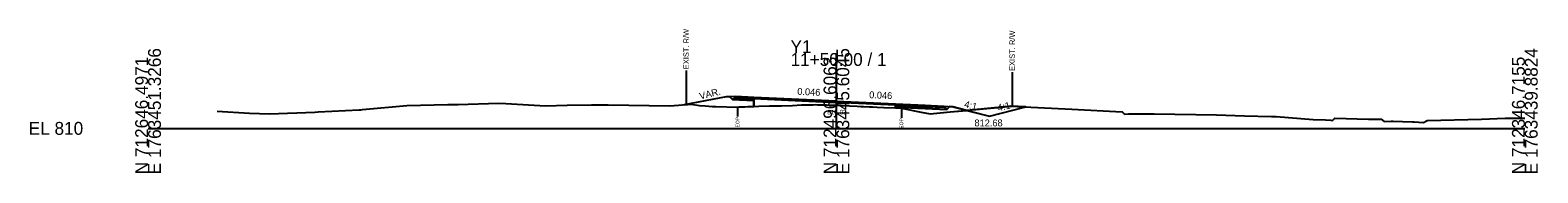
# Model space of a CAD drawing. Extents: x -26 to 1303, y -10 to 9524.
# Drawn here: x -25.7 to 302.8, y 1490.3 to 1521.4 of the extents above; entities that cross this region are included whole.
import ezdxf

# ---------------------------------------------------------------- set-up
doc = ezdxf.new("R2010")
doc.units = 0
for name, color, linetype in [('Default', 7, 'Continuous'), ('Exist CMT Pavement', 7, 'Continuous'), ('Exist Cross Section Cell', 7, 'Continuous'), ('Exist XS Center Line Elevation Label', 7, 'Continuous'), ('Exist XS Ground Line', 7, 'Continuous'), ('Old_Level_10', 7, 'Continuous'), ('Prop CMT Pvmt Course 1', 7, 'Continuous'), ('Prop CMT Pvmt Course 3', 7, 'Continuous'), ('Prop CMT Pvmt Surface', 7, 'Continuous'), ('Prop CMT Pvmt Surface Shoulder', 7, 'Continuous'), ('Prop CMT Shld Paved Course 1', 7, 'Continuous'), ('Prop CMT Shld Paved Course 3', 7, 'Continuous'), ('Prop CMT Slope Grass', 7, 'Continuous'), ('Prop CMT Subgrade Earthwork', 7, 'Continuous'), ('Prop XS Ditch Standard Text', 7, 'Continuous'), ('Prop XS Earthwork Shape', 7, 'Continuous'), ('Prop XS SE Text', 7, 'Continuous'), ('Prop XS Side Slope Text', 7, 'Continuous'), ('Prop XS Wedging', 7, 'Continuous')]:
    doc.layers.add(name, color=color, linetype=linetype)

msp = doc.modelspace()

# ---------------------------------------------------------------- linework, layer by layer
at = {"layer": 'Exist CMT Pavement'}
msp.add_lwpolyline([(132, 1504.78), (133.08, 1504.81), (135.44, 1504.9), (138.04, 1504.94), (140.4, 1505.01), (142.37, 1505.09), (143.9, 1505.11), (144.9, 1505.15), (145.35, 1505.16), (145.84, 1505.14), (147.85, 1505.09), (148.44, 1505.07), (150, 1505.03), (150.36, 1505.02), (151.04, 1504.98), (152.86, 1504.88), (154.54, 1504.82), (155.28, 1504.79), (155.9, 1504.75), (157.19, 1504.7), (157.86, 1504.67), (158.85, 1504.62), (160.36, 1504.56), (162.84, 1504.46), (162.84, 1504.46)], dxfattribs=at)
at = {"layer": 'Exist Cross Section Cell'}
for p, q in [((150, 1500), (150, 1516.4)), ((0, 1500), (150, 1500)), ((150, 1500), (300, 1500))]:
    msp.add_line(p, q, dxfattribs=at)
at = {"layer": 'Exist XS Ground Line'}
msp.add_lwpolyline([(15.03, 1503.71), (22.12, 1503.3), (26.44, 1503.14), (36.35, 1503.54), (37.08, 1503.57), (46.02, 1504.03), (46.36, 1504.07), (46.73, 1504.09), (56.37, 1504.98), (65.3, 1505.17), (66.38, 1505.2), (67.54, 1505.18), (76.39, 1505.47), (77.95, 1505.43), (86.62, 1504.9), (91.31, 1505.06), (96.63, 1505.14), (100.29, 1505.15), (113.66, 1504.93), (118.31, 1505.26), (120.16, 1505), (121.43, 1504.92), (123.02, 1504.75), (123.7, 1504.73), (128.45, 1504.65), (128.79, 1504.67), (129.55, 1504.69), (130.03, 1504.72), (130.71, 1504.75), (131.17, 1504.75), (133.08, 1504.81), (135.44, 1504.9), (138.04, 1504.94), (140.4, 1505.01), (142.37, 1505.09), (143.9, 1505.11), (144.9, 1505.15), (145.35, 1505.16), (145.84, 1505.14), (147.85, 1505.09), (148.44, 1505.07), (150, 1505.03), (150.36, 1505.02), (151.04, 1504.98), (152.86, 1504.88), (154.54, 1504.82), (155.28, 1504.79), (155.9, 1504.75), (157.19, 1504.7), (157.86, 1504.67), (158.85, 1504.62), (160.36, 1504.56), (162.84, 1504.46), (164.16, 1504.37), (168.44, 1503.55), (170.45, 1503.18), (174.78, 1503.58), (185.95, 1504.63), (187.24, 1504.74), (187.96, 1504.83), (201.28, 1504.18), (212.23, 1503.57), (212.74, 1503.07), (213.66, 1503.14), (214.26, 1503.17), (219.25, 1503.19), (232.81, 1502.92), (238.92, 1502.74), (244.78, 1502.58), (245.83, 1502.56), (253.9, 1501.92), (256.58, 1501.82), (257.71, 1501.75), (258.11, 1501.71), (258.62, 1502.2), (265.94, 1501.98), (268.67, 1501.97), (269.33, 1501.47), (270.86, 1501.53), (271.31, 1501.55), (273.33, 1501.51), (275.56, 1501.44), (275.9, 1501.42), (277.93, 1501.27), (278.72, 1501.74), (290.58, 1501.99), (295.72, 1502.25), (300, 1502.2)], dxfattribs=at)
at = {"layer": 'Old_Level_10'}
for p, q in [((117.24, 1512.58), (117.24, 1505.18)), ((188.29, 1512.22), (188.29, 1504.81)), ((128.45, 1504.65), (128.45, 1502.6)), ((164.16, 1504.37), (164.16, 1502.32))]:
    msp.add_line(p, q, dxfattribs=at)
at = {"layer": 'Prop CMT Pvmt Course 1'}
for points in [[(150, 1505.91), (132, 1506.74)], [(132, 1506.74), (132, 1506.49)], [(132, 1506.49), (150, 1505.66)], [(150, 1505.66), (150, 1505.91)], [(150, 1505.91), (169.34, 1505.02)], [(150, 1505.66), (150, 1505.66), (150, 1505.66)], [(162.84, 1505.07), (150, 1505.66)], [(169.34, 1504.77), (162.84, 1505.07)], [(162.84, 1505.07), (162.84, 1505.07)], [(169.34, 1505.02), (169.34, 1504.77)]]:
    msp.add_lwpolyline(points, dxfattribs=at)
at = {"layer": 'Prop CMT Pvmt Course 3'}
for points in [[(132, 1506.49), (132, 1506.07)], [(162.84, 1505.07), (169.34, 1504.77)], [(162.84, 1504.65), (162.84, 1505.07)], [(169.34, 1504.77), (169.34, 1504.35)], [(169.34, 1504.35), (162.84, 1504.65)]]:
    msp.add_lwpolyline(points, dxfattribs=at)
at = {"layer": 'Prop CMT Pvmt Surface'}
for points in [[(150, 1505.91), (132, 1506.74)], [(150, 1505.91), (169.34, 1505.02)]]:
    msp.add_lwpolyline(points, dxfattribs=at)
at = {"layer": 'Prop CMT Pvmt Surface Shoulder'}
for points in [[(132, 1506.74), (128, 1506.92)], [(169.34, 1505.02), (173.34, 1504.84)]]:
    msp.add_lwpolyline(points, dxfattribs=at)
at = {"layer": 'Prop CMT Shld Paved Course 1'}
for points in [[(132, 1506.74), (128, 1506.92), (127.76, 1506.68)], [(127.76, 1506.68), (132, 1506.49)], [(132, 1506.49), (132, 1506.74)], [(169.34, 1505.02), (173.34, 1504.84), (173.61, 1504.58)], [(169.34, 1504.77), (169.34, 1505.02)], [(173.61, 1504.58), (169.34, 1504.77)]]:
    msp.add_lwpolyline(points, dxfattribs=at)
at = {"layer": 'Prop CMT Shld Paved Course 3'}
for points in [[(127.76, 1506.68), (127.36, 1506.28)], [(127.36, 1506.28), (132, 1506.07)], [(132, 1506.49), (127.76, 1506.68)], [(132, 1506.15), (132, 1506.49)], [(169.34, 1504.77), (173.61, 1504.58)], [(169.34, 1504.44), (169.34, 1504.77)], [(174.04, 1504.14), (169.34, 1504.35)], [(173.61, 1504.58), (174.04, 1504.14)]]:
    msp.add_lwpolyline(points, dxfattribs=at)
at = {"layer": 'Prop CMT Slope Grass'}
for points in [[(128, 1506.92), (126, 1506.89), (116.79, 1505.15)], [(173.34, 1504.84), (175.34, 1504.68), (183.34, 1502.68), (191.3, 1504.67)]]:
    msp.add_lwpolyline(points, dxfattribs=at)
at = {"layer": 'Prop CMT Subgrade Earthwork'}
for p, q in [((132, 1506.07), (127.36, 1506.28)), ((132, 1506.07), (132, 1504.78)), ((162.84, 1504.46), (162.84, 1504.65)), ((162.84, 1504.65), (169.34, 1504.35)), ((169.34, 1504.35), (174.04, 1504.14))]:
    msp.add_line(p, q, dxfattribs=at)
for points in [[(126.74, 1506.9), (127.36, 1506.28)], [(174.64, 1504.73), (174.04, 1504.14)]]:
    msp.add_lwpolyline(points, dxfattribs=at)
at = {"layer": 'Prop XS Earthwork Shape'}
for points in [[(121.43, 1504.92), (123.02, 1504.75), (123.7, 1504.73), (128.45, 1504.65), (128.79, 1504.67), (129.55, 1504.69), (130.03, 1504.72), (130.71, 1504.75), (131.17, 1504.75), (132, 1504.78), (132, 1506.07), (127.36, 1506.28), (126.74, 1506.9), (126, 1506.89), (116.79, 1505.15), (118.31, 1505.26), (120.16, 1505)], [(174.64, 1504.73), (174.04, 1504.14), (169.34, 1504.35), (162.84, 1504.65), (162.84, 1504.46), (164.16, 1504.37), (168.44, 1503.55), (170.45, 1503.18), (174.78, 1503.58), (178.39, 1503.92), (175.34, 1504.68)], [(183.34, 1502.68), (191.3, 1504.67), (187.96, 1504.83), (187.24, 1504.74), (185.95, 1504.63), (178.39, 1503.92)]]:
    msp.add_lwpolyline(points, close=True, dxfattribs=at)
at = {"layer": 'Prop XS Wedging'}
for p, q in [((132, 1506.15), (132, 1505.82)), ((132, 1505.82), (132, 1504.78)), ((132, 1504.78), (133.08, 1504.81)), ((133.08, 1504.81), (135.44, 1504.9)), ((135.44, 1504.9), (138.04, 1504.94)), ((138.04, 1504.94), (140.4, 1505.01)), ((140.4, 1505.01), (142.37, 1505.09)), ((142.37, 1505.09), (143.9, 1505.11)), ((147.85, 1505.09), (148.44, 1505.07)), ((148.44, 1505.07), (150, 1505.03)), ((150, 1505.03), (150.36, 1505.02)), ((150.36, 1505.02), (151.04, 1504.98)), ((162.84, 1504.46), (162.84, 1504.74)), ((157.86, 1504.67), (158.85, 1504.62)), ((158.85, 1504.62), (160.36, 1504.56)), ((160.36, 1504.56), (162.84, 1504.46))]:
    msp.add_line(p, q, dxfattribs=at)
for points in [[(162.84, 1504.74), (162.84, 1505.07), (132, 1506.49), (132, 1506.15)], [(143.9, 1505.11), (144.9, 1505.15), (145.35, 1505.16)], [(145.35, 1505.16), (145.84, 1505.14), (147.85, 1505.09)], [(151.04, 1504.98), (152.86, 1504.88), (154.54, 1504.82)], [(154.54, 1504.82), (155.28, 1504.79), (155.9, 1504.75)], [(155.9, 1504.75), (157.19, 1504.7), (157.86, 1504.67)]]:
    msp.add_lwpolyline(points, dxfattribs=at)

# ---------------------------------------------------------------- texts
at = {"layer": 'Default'}
msp.add_text('-', height=0.0001, dxfattribs=at).set_placement((0, 1500))
at = {"layer": 'Exist Cross Section Cell'}
for s, p in [('Y1', (140, 1516.4)), ('11+50.00 / 1', (140, 1513.6)), ('EL 810', (-26, 1498.6))]:
    msp.add_text(s, height=2.8, dxfattribs=at).set_placement(p)
for s, p in [('N 712646.4971', (0, 1490)), ('E 1763451.3266', (2.8, 1490)), ('N 712496.6063', (150, 1490)), ('E 1763445.6045', (152.8, 1490)), ('N 712346.7155', (300, 1490)), ('E 1763439.8824', (302.8, 1490))]:
    msp.add_text(s, height=2.8, rotation=90, dxfattribs=at).set_placement(p)
at = {"layer": 'Exist XS Center Line Elevation Label'}
msp.add_text('815.03', height=1, dxfattribs=at).set_placement((148, 1503.03))
at = {"layer": 'Old_Level_10'}
for s, height, p in [('EXIST. R/W', 1.181, (117.83, 1512.89)), ('EXIST. R/W', 1.181, (188.88, 1512.52)), ('EOP', 0.787, (128.85, 1500.2)), ('EOP', 0.787, (164.55, 1499.92))]:
    msp.add_text(s, height=height, rotation=90, dxfattribs=at).set_placement(p)
at = {"layer": 'Prop XS Ditch Standard Text'}
msp.add_text('812.68', height=1.5, dxfattribs=at).set_placement((180.08, 1500.43))
at = {"layer": 'Prop XS SE Text'}
for p in [(141.44, 1507.31), (157.11, 1506.58)]:
    msp.add_text('0.046', height=1.5, rotation=357.3692, dxfattribs=at).set_placement(p)
at = {"layer": 'Prop XS Side Slope Text'}
for s, rotation, p in [('VAR.', 14.0362, (120.34, 1506.25)), ('4:1', 345.9637, (177.74, 1504.61)), ('4:1', 14.0363, (185.3, 1503.69))]:
    msp.add_text(s, height=1.5, rotation=rotation, dxfattribs=at).set_placement(p)

doc.saveas('drawing.dxf')
